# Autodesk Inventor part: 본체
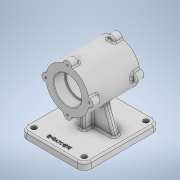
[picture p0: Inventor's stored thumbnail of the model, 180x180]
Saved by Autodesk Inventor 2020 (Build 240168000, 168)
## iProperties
Created: 2022-11
Part Number: 본체
Material: 일반
Document SubType Name: Modeling
Designer: Owner
Density: 1 g/cm^3
Appearance: 기본값
Mass: 450.151 g
Surface Area: 796.911 cm^2
Volume: 450.151 cm^3
Author: Owner
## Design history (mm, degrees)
sketch "스케치1"
  geometry: C1 r 37 at (0, 0); 1 further point
  constraints: 1 centre point, 1 coincident
  dimensions: "d0" = 74 diameter of C1
extrude "돌출1" new body sketch "스케치1" stored distance "d1" = 87; taper "d2" = 0 deg
sketch "스케치2"
  geometry: C1 r 37 at (0, 0) reference; 2 further points
  constraints: 1 coincident
hole "구멍1" sketch "스케치2" at (0, 0) diameter "d3" = 42; stored, may be unused: countersink angle "d7" = 90 deg, drill point angle "d9" = 0 deg; dims "d4" = 8, "d5" = 47, "d6" = 19, "d8" = 10
sketch "스케치3"
  geometry: C1 r 37 at (0, 0) reference; 2 further points
  constraints: 1 coincident
hole "구멍2" sketch "스케치3" at (0, 0) diameter "d10" = 47; stored, may be unused: countersink angle "d14" = 90 deg, drill point angle "d16" = 0 deg; dims "d11" = 8, "d12" = 47, "d13" = 19, "d15" = 19
node "작업 평면1"
sketch "스케치4"
  geometry: L1 (-55, 70)-(55, 70); L2 (55, 70)-(55, -60); L3 (55, -60)-(-55, -60); L4 (-55, -60)-(-55, 70); 2 further points
  constraints: 8 end point, 2 parallel, 1 horizontal, 1 midpoint, 1 perpendicular, 1 vertical alignment
  dimensions: "d18" = 130 distance of L3.end L1.start; "d19" = 110 distance of L2.end L3.end; "d20" = 70 distance from line of L1 point (0, 0)
extrude "돌출2" join sketch "스케치4" distance "d21" = 12; taper "d22" = 0 deg
fillet "모깎기1" dims "d23" = 12
sketch "스케치5"
  geometry: A1 r 12 centre (43, 48) between (55, 48) and (43, 60) reference; A2 r 12 centre (43, -58) between (43, -70) and (55, -58) reference; A3 r 12 centre (-43, -58) between (-55, -58) and (-43, -70) reference; A4 r 12 centre (-43, 48) between (-43, 60) and (-55, 48) reference; 5 further points
  constraints: 4 coincident
hole "구멍3" sketch "스케치5" at (43, 48), (43, -58), (-43, -58), (-43, 48) diameter "d24" = 9; stored, may be unused: countersink angle "d28" = 90 deg, drill point angle "d30" = 0 deg; dims "d25" = 8, "d26" = 47, "d27" = 19, "d29" = 19
sketch "스케치6"
  geometry: L1 (-41, -70)-(41, -70); L2 (43, -70)-(-43, -70) reference; L3 (-55, -82)-(-55, -70) reference; L4 (-41, -70)-(-25.336, -26.964); L5 (41, -70)-(25.336, -26.964); L6 (-47.5, -70)-(-38.5, -70) reference; L7 (43, -70)-(55, -70) reference; A1 r 37 centre (0, 0) between (-25.336, -26.964) and (25.336, -26.964) reference; 3 further points
  constraints: 6 end point, 3 midpoint, 2 point on circle, 1 horizontal, 1 vertical alignment
  dimensions: "d31" = 14 distance from line of L3 L1.start; "d32" = 110 deg angle of L6 L4; "d33" = 110 deg angle of L7 L5
extrude "돌출3" join sketch "스케치6" stored distance "d34" = 10; taper "d35" = 0 deg
sketch "스케치7"
  geometry: L1 (-37, 43.5)-(-37, -43.5) reference; L2 (-70, 5)-(-70, -5) reference; L3 (-70, 0)-(-70, -20); L4 (-70, -20)-(-37, -20); 1 further point
  constraints: 4 end point, 1 collinear, 1 midpoint, 1 perpendicular, 1 point on line
  dimensions: "d37" = 20 distance of L3.start L3.end
sketch "스케치8"
  geometry: C1 r 7 at (0, 37); 4 further points
  constraints: 1 centre point, 1 vertical alignment, 2 other
  dimensions: "d38" = 14 diameter of C1
extrude "돌출4" join sketch "스케치8" distance "d39" = 14; taper "d40" = 0 deg
sketch "스케치9"
  geometry: A1 r 7 centre (0, 37) between (6.969, 36.338) and (-6.969, 36.338) reference; 2 further points
  constraints: 1 coincident
hole "구멍4" sketch "스케치9" at (0, 37) diameter "d41" = 3.242; stored, may be unused: countersink angle "d45" = 90 deg, drill point angle "d47" = 118 deg; dims "d42" = 8, "d43" = 47, "d44" = 19, "d46" = 10
feature "리브1" dims "d51" = 1, "d52" = 10, "d53" = 0, "d54" = 0, "d55" = 1, "d56" = 1
sketch "스케치10"
  geometry: L1 (-77, 0)-(77, 0) reference; L2 (7, -43.5)-(-7, -43.5) reference; 5 further points
  constraints: 1 midpoint, 1 vertical alignment, 1 other
  dimensions: "d57" = 58 distance from line of point (0, -58) L1
feature "엠보싱1" sketch "스케치10" dims "d1" = 87, "d2" = 0, "d18" = 130, "d19" = 110, "d20" = 70, "d58" = 0.5, "d59" = 0
fillet "모깎기2" dims "d60" = 3
fillet "모깎기3" dims "d61" = 3
fillet "모깎기4" dims "d62" = 3
fillet "모깎기5" dims "d63" = 3
chamfer "모따기1" distance "d64" = 1; stored, may be unused: second distance "d65" = 2, angle "d66" = 45 deg
fillet "모깎기6" dims "d67" = 1
node "솔리드1"
pattern_circular "원형 패턴1" dims angle "d49" = 360 deg
mirror "미러1"
mirror "미러2"
feature "A9D066F2-1C7D-4E18-AEED-F7BC21143FA4" dims "d3" = 42, "d4" = 8, "d5" = 47, "d6" = 19, "d7" = 90 deg, "d8" = 10, "d9" = 0
other parameters: "d17" = -82
